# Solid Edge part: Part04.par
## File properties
Author: Robert a Rhodes jr
Template: Normal.par
Last saved by: Cadcim
Revision: 3
Application: Solid Edge
Accuracy: 0.99
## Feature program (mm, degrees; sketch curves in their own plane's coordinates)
body "unnamed Body 1"
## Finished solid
Body 1: solid body, 43 faces, 102 edges, 68 vertices.
  Faces by surface: cylinder 28, plane 15
  Edges by curve: circle 56, line 46
Bounding box of the edges (mm): 1353.852 x 457.200 x 1295.400, from (-676.9261, -203.2, -533.4) to (676.9261, 254, 762).
Cylindrical faces by radius (mm): R50.8 x6, R95.25 x6, R127 x5, R152.4 x2, R254 x2, R431.8 x2, R508 x2, R533.4 x3
Planar faces by outward normal: +x 1, +y 7, -x 1, -y 2, oblique 4
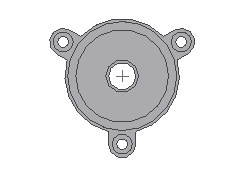
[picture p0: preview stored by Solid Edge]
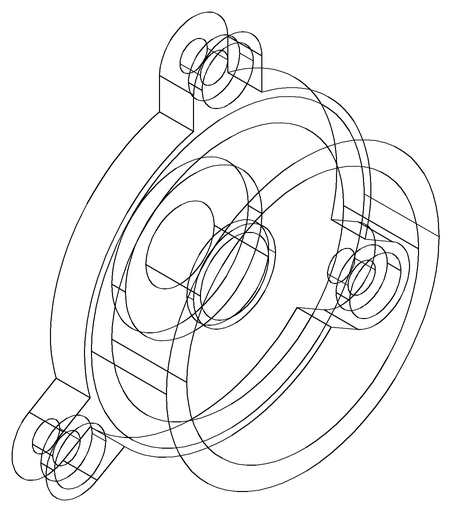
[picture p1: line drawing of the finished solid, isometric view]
